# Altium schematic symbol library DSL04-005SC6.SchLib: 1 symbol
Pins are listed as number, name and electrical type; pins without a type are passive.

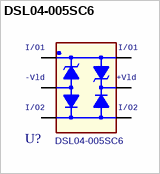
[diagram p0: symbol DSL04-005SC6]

## DSL04-005SC6
designator U?
footprint ST_SOT23-6L
pins: 1 I/O1, 2 -Vld, 3 I/O2, 4 I/O2b, 5 +Vld, 6 I/O1b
